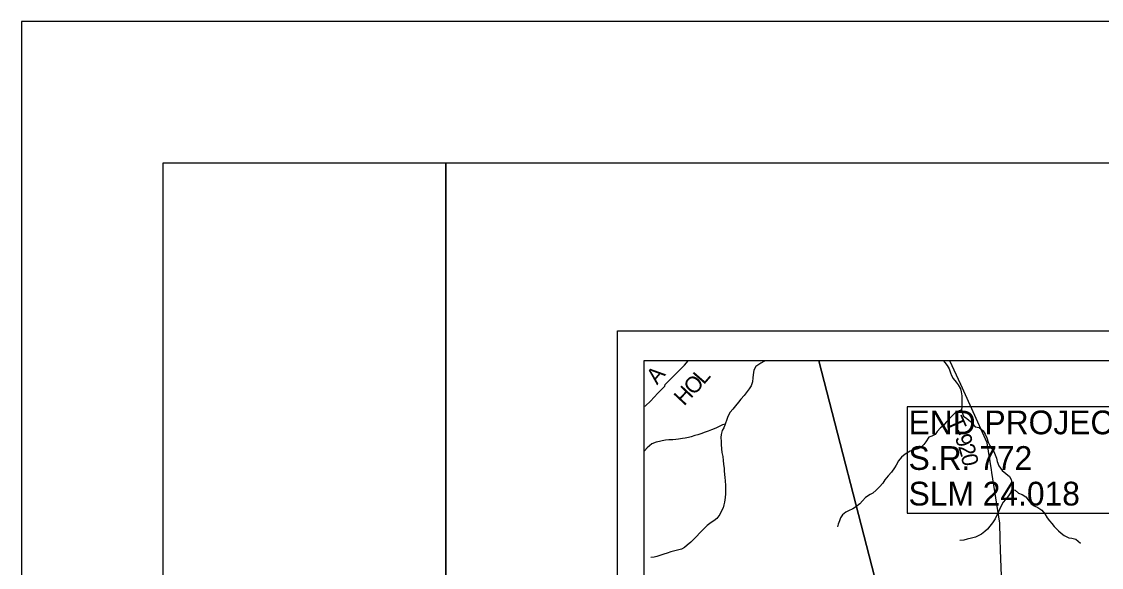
# Model space of a CAD drawing. Extents: x 0 to 34, y 0 to 22.
# Drawn here: x 0 to 3.817, y 20.069 to 22 of the extents above; entities that cross this region are included whole.
import ezdxf

# ---------------------------------------------------------------- set-up
doc = ezdxf.new("R2010")
doc.units = 0
for name, color, linetype in [('Default', 7, 'Continuous'), ('GM_X_Minor_River', 7, 'Continuous'), ('GM_X_Township_Road', 7, 'Continuous'), ('GM_X_Township_Road_Text', 7, 'Continuous'), ('SH_Border', 7, 'Continuous'), ('SH_Cut_Line', 7, 'Continuous'), ('SH_Text', 7, 'Continuous')]:
    doc.layers.add(name, color=color, linetype=linetype)

msp = doc.modelspace()

# ---------------------------------------------------------------- linework, layer by layer
at = {"layer": 'Default'}
for points in [[(9.087, 13.8822), (2.1062, 13.8822), (2.1062, 20.9054), (9.087, 20.9054)], [(2.8183, 20.8), (2.2, 20.8), (2.2, 19.4329), (2.7961, 19.3885), (3.1893, 19.3592), (3.0244, 19.9995)], [(5.8621, 20.8), (2.8183, 20.8), (3.0244, 19.9995), (3.1893, 19.3592), (4.7641, 19.2419), (4.831, 19.2363), (5.1554, 19.2083), (5.1782, 19.2598), (5.5496, 20.1004), (5.5679, 20.1313), (5.5783, 20.1528), (5.5834, 20.1771), (5.5869, 20.1933), (5.5951, 20.2127), (5.6047, 20.2229), (5.6166, 20.2359)]]:
    msp.add_lwpolyline(points, close=True, dxfattribs=at)
at = {"layer": 'GM_X_Minor_River'}
for points in [[(2.6295, 20.8), (2.6236, 20.7973), (2.6129, 20.791), (2.5962, 20.7794), (2.5892, 20.7662), (2.5864, 20.7499), (2.5855, 20.7401), (2.5834, 20.7257), (2.5787, 20.7113), (2.5726, 20.7011), (2.5656, 20.691), (2.5545, 20.6771), (2.543, 20.6639), (2.5346, 20.6534), (2.5238, 20.6406), (2.515, 20.629), (2.5054, 20.6177), (2.4973, 20.6022), (2.4934, 20.5917), (2.4871, 20.575), (2.4821, 20.563), (2.477, 20.5532), (2.4727, 20.5388), (2.4722, 20.5289), (2.4736, 20.5141), (2.4738, 20.5035), (2.4748, 20.4879), (2.4761, 20.4758), (2.4786, 20.4606), (2.4803, 20.4473), (2.4817, 20.4336), (2.4834, 20.4192), (2.4841, 20.4089), (2.4864, 20.3869), (2.4874, 20.3755), (2.488, 20.3588), (2.4886, 20.3478), (2.4889, 20.3383), (2.4884, 20.3288), (2.4875, 20.3159), (2.485, 20.3), (2.483, 20.2898), (2.4803, 20.28), (2.4749, 20.2687), (2.469, 20.2562), (2.4575, 20.2419), (2.4472, 20.2341), (2.4377, 20.2281), (2.4243, 20.2165), (2.4102, 20.2042), (2.3976, 20.1907), (2.3864, 20.1787), (2.3654, 20.1584), (2.3536, 20.1476)], [(3.2595, 20.8), (3.2645, 20.7943), (3.2727, 20.7832), (3.279, 20.771), (3.2837, 20.7573), (3.2881, 20.7474), (3.2933, 20.7375), (3.3041, 20.7244), (3.3116, 20.7145)], [(3.3116, 20.7145), (3.3194, 20.7007), (3.3219, 20.6897), (3.3236, 20.6756), (3.3242, 20.6624), (3.3241, 20.6495), (3.3235, 20.6369), (3.3226, 20.626), (3.3259, 20.6134), (3.3303, 20.6039), (3.3423, 20.5954), (3.3543, 20.585), (3.3629, 20.5754), (3.3711, 20.5658), (3.3851, 20.5641), (3.3997, 20.5518), (3.4063, 20.5404), (3.4122, 20.5274), (3.4177, 20.5118), (3.4218, 20.5019), (3.4273, 20.4919), (3.4366, 20.4793), (3.4418, 20.4671), (3.4462, 20.4549), (3.4495, 20.4439), (3.4546, 20.4283), (3.4665, 20.4114), (3.4796, 20.401), (3.4923, 20.3899), (3.4979, 20.3796), (3.5008, 20.3697), (3.5017, 20.3568), (3.5008, 20.3442), (3.4962, 20.3322), (3.4892, 20.322), (3.4781, 20.3096), (3.4697, 20.2991), (3.4639, 20.2889), (3.4569, 20.2734), (3.4526, 20.2636), (3.448, 20.2538), (3.4418, 20.241), (3.4329, 20.2263), (3.4233, 20.2147), (3.4149, 20.2041), (3.4053, 20.1963), (3.3935, 20.1866), (3.3817, 20.1802), (3.3722, 20.1762), (3.3585, 20.1722), (3.3434, 20.1682), (3.3309, 20.1657), (3.3165, 20.1639)], [(3.3226, 20.626), (3.3128, 20.6211), (3.3033, 20.6178), (3.291, 20.6066), (3.2815, 20.5965), (3.2684, 20.5822), (3.2589, 20.5713), (3.2489, 20.5623), (3.2371, 20.5496), (3.2294, 20.5394), (3.2183, 20.5335), (3.2073, 20.5294), (3.1973, 20.5136), (3.1896, 20.5035), (3.1774, 20.4922), (3.1649, 20.4871), (3.1554, 20.4845), (3.1417, 20.4797), (3.1238, 20.4689), (3.1112, 20.4592), (3.1001, 20.4457), (3.0923, 20.4302), (3.0858, 20.4205), (3.0754, 20.4062), (3.0632, 20.393), (3.0517, 20.3784), (3.0451, 20.3667), (3.0332, 20.3539), (3.0214, 20.3423), (3.0099, 20.3314), (3.0004, 20.3266), (2.9836, 20.3166), (2.9725, 20.3049), (2.9629, 20.294), (2.9484, 20.2821), (2.9382, 20.2765), (2.9233, 20.2695), (2.9138, 20.2643), (2.9024, 20.2549), (2.895, 20.244), (2.8911, 20.2334), (2.8872, 20.2221), (2.8841, 20.2119)], [(2.4871, 20.575), (2.4777, 20.5733), (2.464, 20.5658), (2.4544, 20.561), (2.4396, 20.5551), (2.4271, 20.5507), (2.4169, 20.5478), (2.4013, 20.5408), (2.391, 20.5379), (2.3797, 20.5353), (2.3675, 20.5305), (2.3573, 20.5288), (2.3455, 20.5262), (2.336, 20.5245), (2.3228, 20.5223), (2.3129, 20.5217), (2.3023, 20.5207), (2.288, 20.5197), (2.2766, 20.5187), (2.2645, 20.5162), (2.255, 20.5144), (2.244, 20.5123), (2.2284, 20.5064), (2.2112, 20.4914), (2.2017, 20.4813), (2.2, 20.4799)], [(3.5008, 20.3442), (3.5122, 20.3418), (3.5238, 20.3318), (3.5369, 20.3271), (3.5501, 20.3186), (3.5616, 20.3037), (3.5695, 20.2941), (3.5792, 20.2864), (3.5924, 20.2806), (3.6066, 20.2709), (3.6174, 20.2586), (3.6263, 20.2441), (3.6345, 20.2334), (3.6427, 20.2238), (3.6509, 20.2135), (3.6655, 20.1985), (3.6752, 20.1897), (3.6857, 20.182), (3.7019, 20.1738), (3.7125, 20.1722), (3.7272, 20.1682), (3.7433, 20.1547)], [(2.3536, 20.1476), (2.3436, 20.1393), (2.3326, 20.133), (2.3193, 20.1301), (2.3095, 20.128), (2.2947, 20.1236), (2.2818, 20.1188), (2.2708, 20.1155), (2.2597, 20.1119), (2.2457, 20.1078), (2.2358, 20.1049), (2.2245, 20.1035)]]:
    msp.add_lwpolyline(points, dxfattribs=at)
at = {"layer": 'GM_X_Township_Road'}
for points in [[(2.2654, 20.7013), (2.2728, 20.7088), (2.2735, 20.7095), (2.2754, 20.7163), (2.3438, 20.7847), (2.3565, 20.8)], [(3.4292, 20.4138), (3.4142, 20.5097), (3.3206, 20.7164), (3.2818, 20.8)], [(2.2, 20.6394), (2.2054, 20.6409), (2.2239, 20.6564), (2.2492, 20.685), (2.2654, 20.7013)], [(3.46, 20.1696), (3.4588, 20.2255), (3.4306, 20.4051), (3.4292, 20.4138)], [(3.4596, 19.9234), (3.4653, 20.0088), (3.4608, 20.1294), (3.46, 20.1696)]]:
    msp.add_lwpolyline(points, dxfattribs=at)
at = {"layer": 'SH_Border'}
for points in [[(0.5, 21.5), (1.5, 21.5), (1.5, 0.5), (0.5, 0.5)], [(1.5, 21.5), (33.5, 21.5), (33.5, 0.5), (1.5, 0.5)]]:
    msp.add_lwpolyline(points, close=True, dxfattribs=at)
at = {"layer": 'SH_Cut_Line'}
for points in [[(0, 0), (34, 0), (34, 22), (0, 22)], [(9, 18.8941), (9, 20.8), (2.2, 20.8), (2.2, 19.4329), (2.7961, 19.3885), (3.1893, 19.3592), (4.7641, 19.2419), (4.831, 19.2363), (5.1554, 19.2083), (5.3224, 19.1939), (5.8337, 19.1499), (6.226, 19.1161), (6.8442, 19.0679), (8.0305, 18.9725), (8.8762, 18.9027)]]:
    msp.add_lwpolyline(points, close=True, dxfattribs=at)
at = {"layer": 'SH_Text'}
msp.add_lwpolyline([(3.9194, 20.6364), (3.1311, 20.6364), (3.1311, 20.2602), (3.9194, 20.2602)], close=True, dxfattribs=at)

# ---------------------------------------------------------------- texts
at = {"layer": 'GM_X_Township_Road_Text'}
for s, rotation, p in [('A', 49.9775, (2.2467, 20.7128)), ('O', 47.5019, (2.3765, 20.675)), ('L', 48.976, (2.4114, 20.7131)), ('H', 46.9, (2.3419, 20.638)), ('T', 293.9262, (3.2716, 20.5876)), ('9', 291.5729, (3.2981, 20.528)), ('-', 293.9262, (3.2888, 20.5487)), ('2', 286.8662, (3.3105, 20.4966)), ('0', 282.1595, (3.3204, 20.4643))]:
    msp.add_text(s, height=0.0568, rotation=rotation, dxfattribs=at).set_placement(p)
at = {"layer": 'SH_Text'}
for s, p in [('END PROJECT', (3.1358, 20.5398)), ('S.R. 772          ', (3.1358, 20.4138)), ('SLM 24.018     ', (3.1358, 20.2878))]:
    msp.add_text(s, height=0.084, dxfattribs=at).set_placement(p)

doc.saveas('drawing.dxf')
